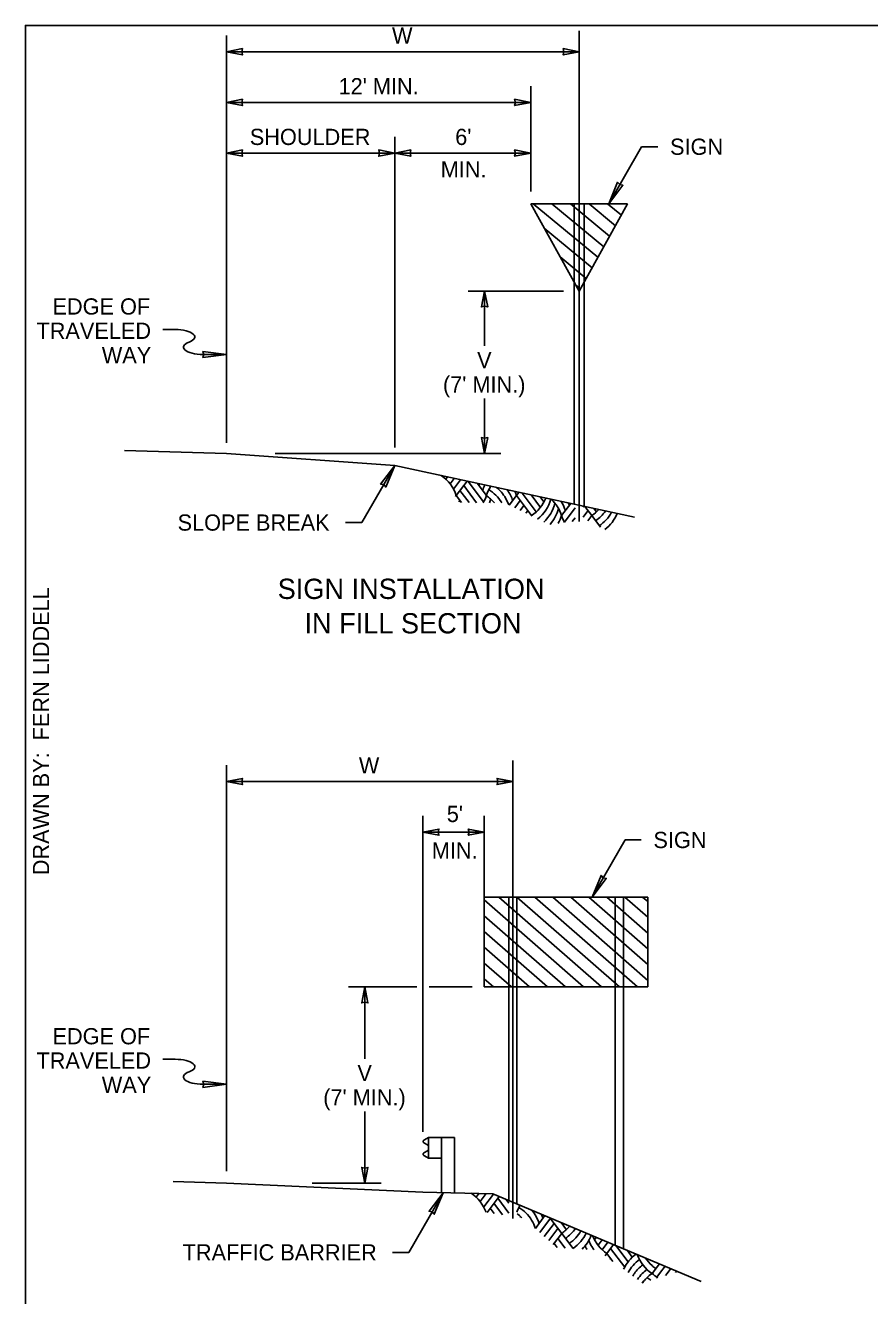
# Model space of a CAD drawing. Extents: x 99862 to 104211, y 98939 to 102076.
# Drawn here: x 99862 to 100694, y 100822 to 102076 of the extents above; entities that cross this region are included whole.
import ezdxf

# ---------------------------------------------------------------- set-up
doc = ezdxf.new("R2010")
doc.units = 0
for name, color, linetype in [('Level 1', 7, 'Continuous'), ('Level 14', 7, 'Continuous'), ('Level 15', 7, 'Continuous'), ('Level 2', 7, 'Continuous'), ('Level 20', 7, 'Continuous'), ('Level 6', 7, 'Continuous'), ('Level 62', 7, 'Continuous')]:
    doc.layers.add(name, color=color, linetype=linetype)

msp = doc.modelspace()

# ---------------------------------------------------------------- linework, layer by layer
at = {"layer": 'Level 1'}
msp.add_lwpolyline([(99862, 99999.5), (103151, 99999.5), (103151, 102075.5), (99862, 102075.5)], close=True, dxfattribs=at)
msp.add_lwpolyline([(99862, 99999.5), (103151, 99999.5), (103151, 102075.5), (99862, 102075.5)], close=True, dxfattribs=at)
at = {"layer": 'Level 14'}
for p, q in [((100009.7, 101775.4), (99997.4, 101775.4)), ((100056.2, 101750.8), (100037, 101750.8)), ((100009.7, 101055.4), (99997.4, 101055.4)), ((100056.2, 101030.8), (100037, 101030.8))]:
    msp.add_line(p, q, dxfattribs=at)
for points in [[(100060.3, 101750.8), (100036.9, 101747.8), (100038, 101750.8), (100036.9, 101753.9)], [(100060.3, 101030.8), (100036.9, 101027.7), (100038, 101030.8), (100036.9, 101033.8)]]:
    msp.add_lwpolyline(points, close=True, dxfattribs=at)
for centre, start_param, end_param in [((100009.8, 101768.2), 5.497747, 7.861127), ((100037, 101758), 2.356226, 4.712389), ((100009.8, 101048.2), 5.497747, 7.861127), ((100037, 101038), 2.356226, 4.712389)]:
    msp.add_ellipse(centre, major_axis=(19.2, 0), ratio=0.375, start_param=start_param, end_param=end_param, dxfattribs=at)
at = {"layer": 'Level 15'}
for p, q in [((100060.3, 102065.5), (100060.3, 101663.8)), ((100407.9, 102049.5), (100060.3, 102049.5)), ((100360.1, 102015.5), (100360.1, 101911.5)), ((100360.1, 101999.5), (100060.3, 101999.5)), ((100226.2, 101965.5), (100226.2, 101659.1)), ((100437, 101899.5), (100469.5, 101955.8)), ((100469.5, 101955.8), (100485.5, 101955.8)), ((100226.2, 101949.5), (100060.3, 101949.5)), ((100360.1, 101949.5), (100226.2, 101949.5)), ((100298.6, 101813.4), (100392.6, 101813.4)), ((100314.6, 101813.4), (100314.6, 101759.3)), ((100314.6, 101707.3), (100314.6, 101653.1)), ((100108.3, 101653.1), (100330.6, 101653.1)), ((100226.2, 101641.3), (100193.7, 101585)), ((100177.7, 101585), (100193.7, 101585)), ((100060.3, 101345.5), (100060.3, 100945.1)), ((100342.6, 101329.5), (100060.3, 101329.5)), ((100253.9, 101295.5), (100253.9, 100983.7)), ((100314.3, 101295.5), (100314.3, 101199)), ((100314.3, 101279.5), (100253.9, 101279.5)), ((100420.6, 101215.5), (100453.1, 101271.8)), ((100453.1, 101271.8), (100469.1, 101271.8)), ((100180.6, 101126.8), (100247.9, 101126.8)), ((100196.6, 101126.8), (100196.6, 101055.9)), ((100259.9, 101126.8), (100302.3, 101126.8)), ((100196.6, 101003.9), (100196.6, 100933.1)), ((100144.8, 100933.1), (100212.6, 100933.1)), ((100273.9, 100923.8), (100239.9, 100864.9)), ((100223.9, 100864.9), (100239.9, 100864.9))]:
    msp.add_line(p, q, dxfattribs=at)
for points in [[(100060.3, 102049.5), (100076, 102046.4), (100075.3, 102049.5), (100076, 102052.6)], [(100407.9, 102049.5), (100392.2, 102046.4), (100392.9, 102049.5), (100392.2, 102052.6)], [(100060.3, 101999.5), (100076, 101996.4), (100075.3, 101999.5), (100076, 102002.6)], [(100360.1, 101999.5), (100344.3, 101996.4), (100345.1, 101999.5), (100344.3, 102002.6)], [(100060.3, 101949.5), (100076, 101946.4), (100075.3, 101949.5), (100076, 101952.6)], [(100226.2, 101949.5), (100210.4, 101946.4), (100211.2, 101949.5), (100210.4, 101952.6)], [(100226.2, 101949.5), (100241.9, 101946.4), (100241.2, 101949.5), (100241.9, 101952.6)], [(100360.1, 101949.5), (100344.3, 101946.4), (100345.1, 101949.5), (100344.3, 101952.6)], [(100092.3, 101949.5), (100092.3, 101949.5), (100092.3, 101949.5), (100092.3, 101949.5)], [(100092.3, 101949.5), (100092.3, 101949.5), (100092.3, 101949.5), (100092.3, 101949.5)], [(100226.2, 101949.5), (100226.2, 101949.5), (100226.2, 101949.5), (100226.2, 101949.5)], [(100226.2, 101949.5), (100226.2, 101949.5), (100226.2, 101949.5), (100226.2, 101949.5)], [(100437, 101899.5), (100451, 101917.8), (100447.9, 101918.4), (100445.8, 101920.8)], [(100314.6, 101813.4), (100311.5, 101797.7), (100314.6, 101798.4), (100317.7, 101797.7)], [(100314.6, 101653.1), (100311.5, 101668.8), (100314.6, 101668.1), (100317.7, 101668.8)], [(100226.2, 101641.3), (100217.3, 101620), (100215.3, 101622.4), (100212.2, 101623)], [(100060.3, 101329.5), (100076, 101326.4), (100075.3, 101329.5), (100076, 101332.5)], [(100342.6, 101329.5), (100326.9, 101326.4), (100327.6, 101329.5), (100326.9, 101332.5)], [(100253.9, 101279.5), (100269.6, 101276.4), (100268.8, 101279.5), (100269.6, 101282.5)], [(100314.3, 101279.5), (100298.6, 101276.4), (100299.3, 101279.5), (100298.6, 101282.5)], [(100420.6, 101215.5), (100429.5, 101236.8), (100431.5, 101234.4), (100434.6, 101233.8)], [(100196.6, 101126.8), (100193.6, 101111.1), (100196.6, 101111.8), (100199.7, 101111.1)], [(100196.6, 100933.1), (100193.6, 100948.8), (100196.6, 100948.1), (100199.7, 100948.8)], [(100273.9, 100923.8), (100265, 100902.5), (100263, 100904.9), (100259.9, 100905.5)]]:
    msp.add_lwpolyline(points, close=True, dxfattribs=at)
at = {"layer": 'Level 2'}
for p, q in [((100407.9, 102070.3), (100407.9, 101586)), ((100360.1, 101899.5), (100455.7, 101899.5)), ((100407.9, 101813.4), (100360.1, 101899.5)), ((100362.6, 101899.5), (100426.4, 101846.7)), ((100380.9, 101899.5), (100432.2, 101857.1)), ((100399.3, 101899.5), (100437.9, 101867.5)), ((100403.1, 101899.5), (100403.1, 101822.3)), ((100407.9, 101813.4), (100455.7, 101899.5)), ((100412.7, 101899.5), (100412.7, 101822)), ((100417.6, 101899.5), (100443.7, 101877.9)), ((100435.9, 101899.5), (100449.5, 101888.3)), ((100373.5, 101875.3), (100420.6, 101836.3)), ((100389.1, 101847.2), (100414.8, 101825.9)), ((100403.1, 101822), (100403.1, 101603)), ((100404.7, 101819.2), (100409.1, 101815.5)), ((100412.7, 101822), (100412.7, 101600.9)), ((100060.3, 101653.1), (99959.8, 101656.2)), ((100060.3, 101653.1), (100226.2, 101641.3)), ((100226.2, 101641.3), (100462.4, 101590.2)), ((100342.6, 101350.3), (100342.6, 100898.4)), ((100314.3, 101215.5), (100314.3, 101126.8)), ((100314.3, 101215.5), (100475.7, 101215.5)), ((100412.1, 101126.8), (100314.3, 101212.6)), ((100429.9, 101126.8), (100328.8, 101215.5)), ((100338.5, 101126.8), (100338.5, 101215.5)), ((100447.6, 101126.8), (100346.5, 101215.5)), ((100346.6, 101126.8), (100346.6, 101215.5)), ((100465.3, 101126.8), (100364.2, 101215.5)), ((100475.7, 101133.2), (100381.9, 101215.5)), ((100475.7, 101148.8), (100399.7, 101215.5)), ((100475.7, 101164.4), (100417.4, 101215.5)), ((100475.7, 101179.9), (100435.1, 101215.5)), ((100443.4, 101126.8), (100443.4, 101215.5)), ((100451.5, 101126.8), (100451.5, 101215.5)), ((100475.7, 101195.5), (100452.8, 101215.5)), ((100475.7, 101211), (100470.5, 101215.5)), ((100475.7, 101215.5), (100475.7, 101126.8)), ((100394.4, 101126.8), (100314.3, 101197.1)), ((100376.7, 101126.8), (100314.3, 101181.5)), ((100359, 101126.8), (100314.3, 101166)), ((100341.3, 101126.8), (100314.3, 101150.4)), ((100323.5, 101126.8), (100314.3, 101134.9)), ((100314.3, 101126.8), (100475.7, 101126.8)), ((100338.5, 101126.8), (100338.5, 100916.1)), ((100346.6, 101126.8), (100346.6, 100912.7)), ((100443.4, 101126.8), (100443.4, 100872)), ((100451.5, 101126.8), (100451.5, 100868.6)), ((100254.8, 100975.7), (100257.8, 100977.4)), ((100254.8, 100973), (100258.5, 100971)), ((100259.3, 100978.2), (100257.8, 100977.4)), ((100259.2, 100978.2), (100285.1, 100978.2)), ((100259.3, 100978.2), (100259.3, 100958)), ((100272.2, 100978.2), (100272.2, 100923.8)), ((100285.1, 100978.2), (100285.1, 100923.6)), ((100254.7, 100960.5), (100257.8, 100958.7)), ((100254.8, 100963.2), (100258.5, 100965.2)), ((100259.3, 100966.5), (100259.3, 100969.6)), ((100259.3, 100958), (100257.8, 100958.7)), ((100259.3, 100958), (100272.2, 100958)), ((100060.3, 100933.1), (100007.6, 100934.7)), ((100060.3, 100933.1), (100253.9, 100924.2)), ((100253.9, 100924.2), (100322.7, 100922.8)), ((100322.7, 100922.8), (100528.1, 100836.3))]:
    msp.add_line(p, q, dxfattribs=at)
for centre, radius, start, end in [((100255.5, 100974.3), 1.55, 118.2399, 241.2772), ((100255.5, 100961.8), 1.55, 118.3269, 239.7049), ((100257.8, 100969.6), 1.54, 359.9913, 61.47), ((100257.8, 100966.5), 1.54, 298.53, 359.9913)]:
    msp.add_arc(centre, radius, start, end, dxfattribs=at)
at = {"layer": 'Level 6'}
for p, q in [((100276.5, 101627.7), (100278.2, 101630)), ((100280.6, 101623.2), (100284.6, 101628.6)), ((100284, 101617.9), (100291, 101627.2)), ((100286.7, 101611.6), (100297.4, 101625.9)), ((100298.4, 101625.6), (100313.7, 101605.3)), ((100290.4, 101616.5), (100299.3, 101604.7)), ((100294.1, 101621.5), (100306.8, 101604.6)), ((100307.3, 101623.7), (100316.4, 101611.6)), ((100346.1, 101611.6), (100348.5, 101614.8)), ((100351.6, 101614.1), (100365.6, 101595.5)), ((100360.5, 101612.2), (100369.7, 101599.9)), ((100285.9, 101610.6), (100286.7, 101611.6)), ((100286.7, 101611.6), (100291.8, 101604.7)), ((100289.4, 101605.3), (100290.4, 101606.6)), ((100339, 101602.1), (100346.1, 101611.6)), ((100344.4, 101599.5), (100349.8, 101606.6)), ((100346.1, 101611.6), (100360.9, 101591.8)), ((100349.8, 101596.8), (100353.5, 101601.7)), ((100369.3, 101610.3), (100373.1, 101605.3)), ((100390.6, 101591.8), (100399.6, 101603.8)), ((100393.3, 101585.5), (100403.9, 101599.6)), ((100411.9, 101600.3), (100412.4, 101601)), ((100413.6, 101600.7), (100420.3, 101591.8)), ((100355.3, 101594.1), (100357.2, 101596.7)), ((100360.7, 101591.5), (100360.9, 101591.8)), ((100360.9, 101591.8), (100361.4, 101591.2)), ((100401.1, 101585.9), (100403.9, 101589.7)), ((100411.9, 101590.4), (100416.6, 101596.7)), ((100416.6, 101586.8), (100420.3, 101591.8)), ((100420.3, 101591.8), (100428.8, 101580.5)), ((100422.5, 101598.8), (100425, 101595.5)), ((100416.6, 101586.8), (100416.6, 101586.8)), ((100306.2, 100919.5), (100308.9, 100923.1)), ((100310.3, 100915.1), (100316.2, 100922.9)), ((100313.8, 100909.8), (100323.3, 100922.5)), ((100317.1, 100904.3), (100329, 100920.2)), ((100323.9, 100913.3), (100332.4, 100902)), ((100327.6, 100918.3), (100338.6, 100903.6)), ((100335.7, 100917.3), (100338.6, 100913.5)), ((100320.1, 100908.4), (100324, 100903.3)), ((100364.7, 100888.6), (100374.1, 100901.2)), ((100369.1, 100884.6), (100379.5, 100898.5)), ((100379.1, 100899), (100390.7, 100883.6)), ((100373.5, 100880.6), (100383.3, 100893.5)), ((100378, 100876.6), (100387, 100888.6)), ((100390, 100894.5), (100395.3, 100887.3)), ((100382.4, 100872.6), (100390.7, 100883.6)), ((100383.3, 100873.7), (100386.3, 100869.7)), ((100387, 100878.7), (100394.1, 100869.2)), ((100390.7, 100883.6), (100401.9, 100868.7)), ((100423.1, 100877.3), (100424.9, 100879.8)), ((100426.5, 100872), (100430.5, 100877.4)), ((100430.6, 100867.5), (100436.2, 100875)), ((100435.2, 100863.8), (100441.8, 100872.6)), ((100433.5, 100861.6), (100435.2, 100863.8)), ((100435.2, 100863.8), (100441.1, 100856)), ((100438.9, 100868.8), (100452.8, 100850.4)), ((100444.2, 100871.6), (100456.2, 100855.7)), ((100455.1, 100867), (100460.3, 100860.1)), ((100438.3, 100858), (100438.9, 100858.9)), ((100479.8, 100844), (100487, 100853.6)), ((100487.2, 100844), (100492.6, 100851.2)), ((100494.6, 100844), (100498.2, 100848.9)), ((100484.4, 100840.3), (100487.2, 100844)), ((100493.1, 100842), (100494.6, 100844)), ((100502.9, 100845.2), (100503.9, 100846.5))]:
    msp.add_line(p, q, dxfattribs=at)
for centre, start, end in [((100250.9, 101600.2), 17.6434, 56.0947), ((100344.8, 101610.1), 159.5467, 162.3566), ((100348.5, 101605.1), 153.2388, 162.3566), ((100352.2, 101600.2), 146.7442, 162.3566), ((100299.1, 101585.4), 31.3316, 58.4874), ((100302.8, 101590.3), 40.9413, 51.2149), ((100302.8, 101590.3), 18.7263, 40.9414), ((100306.6, 101595.2), 17.6434, 35.9283), ((100310.3, 101600.2), 17.6434, 24.3134), ((100280.6, 101623), 330.6518, 342.3566), ((100295.4, 101580.4), 39.8382, 56.0964), ((100284.3, 101618), 338.9197, 345.0113), ((100299.1, 101585.4), 30.4881, 31.3317), ((100340, 101623), 303.9036, 338.33), ((100343.7, 101618), 308.1554, 344.5515), ((100347.4, 101613.1), 312.8471, 346.3199), ((100354.8, 101580.4), 17.6434, 47.0532), ((100358.5, 101585.4), 31.3316, 33.0188), ((100358.5, 101585.4), 17.6434, 31.3317), ((100362.2, 101590.3), 17.6434, 21.868), ((100351.1, 101608.1), 318.4602, 345.7713), ((100354.8, 101603.2), 329.6871, 342.3566), ((100426.4, 101603.2), 197.6435, 208.9334), ((100399.4, 101623), 303.9036, 317.8918), ((100403.1, 101618), 303.9036, 324.7989), ((100406.8, 101613.1), 303.9036, 331.3675), ((100410.5, 101608.1), 307.1427, 337.7201), ((100414.2, 101580.4), 19.0136, 19.4909), ((100422.7, 101598.2), 200.8778, 201.7831), ((100280.6, 100892), 19.3393, 56.0945), ((100381.9, 100892), 148.9555, 160.2414), ((100325.2, 100872.2), 45.5471, 55.2753), ((100328.9, 100877.2), 31.3316, 58.4874), ((100314, 100909.9), 343.631, 345.0113), ((100332.6, 100882.1), 17.6434, 40.6931), ((100336.3, 100887.1), 17.6434, 24.5032), ((100328.9, 100877.2), 17.6658, 31.3317), ((100369.7, 100914.8), 303.9036, 320.3127), ((100373.4, 100909.9), 303.9036, 325.2256), ((100377.1, 100904.9), 303.9036, 330.0509), ((100380.9, 100900), 303.9036, 334.8258), ((100384.6, 100895), 314.2423, 339.5846), ((100452.5, 100890.1), 200.8778, 211.332), ((100456.2, 100895), 201.386, 236.0964), ((100448.8, 100885.1), 201.4344, 207.4578), ((100452.5, 100890.1), 211.3319, 217.2558), ((100485.9, 100832.6), 125.4637, 155.4997), ((100500.7, 100875.2), 199.3972, 236.0964), ((100489.6, 100827.7), 126.3063, 152.7121), ((100493.3, 100822.7), 127.1006, 145.4911), ((100497, 100817.8), 126.331, 135.7128), ((100504.4, 100880.2), 213.4609, 228.9599), ((100504.4, 100880.2), 228.9599, 236.0964), ((100493.3, 100822.7), 145.491, 149.9457), ((100497, 100817.8), 135.7127, 147.1937), ((100500.7, 100812.8), 123.9036, 144.4496), ((100451.4, 100802.9), 58.4099, 59.3021), ((100455.1, 100807.9), 51.5617, 58.5465), ((100458.8, 100812.8), 45.2234, 56.0963)]:
    msp.add_arc(centre, 37.6, start, end, dxfattribs=at)

# ---------------------------------------------------------------- texts
at = {"layer": 'Level 2'}
for s, p in [('SIGN INSTALLATION', (100110.7, 101509.6)), ('IN FILL SECTION', (100137.1, 101475.6))]:
    msp.add_text(s, height=20, dxfattribs=at).set_placement(p)
at = {"layer": 'Level 20'}
for s, p in [('W', (100223.4, 102057.5)), ("12' MIN.", (100170.7, 102007.5)), ('SHOULDER', (100083.2, 101957.5)), ("6'", (100285.7, 101957.5)), ('SIGN', (100497.5, 101947.8)), ('MIN.', (100271.4, 101925.5)), ('EDGE OF', (99888.7, 101790.2)), ('TRAVELED', (99872.9, 101766.2)), ('WAY', (99937.3, 101742.2)), ('V', (100307.3, 101737.3)), ("(7' MIN.)", (100273.6, 101713.3)), ('SLOPE BREAK', (100012, 101577)), ('W', (100190.7, 101337.5)), ("5'", (100277.4, 101289.5)), ('SIGN', (100481.1, 101263.8)), ('MIN.', (100262.6, 101253.5)), ('EDGE OF', (99888.7, 101070.2)), ('TRAVELED', (99872.9, 101046.2)), ('V', (100189.3, 101033.9)), ('WAY', (99937.3, 101022.2)), ("(7' MIN.)", (100155.6, 101009.9)), ('TRAFFIC BARRIER', (100017, 100856.9))]:
    msp.add_text(s, height=16, dxfattribs=at).set_placement(p)
at = {"layer": 'Level 62'}
msp.add_text('DRAWN BY:  FERN LIDDELL', height=16, rotation=90, dxfattribs=at).set_placement((99885.4, 101237))

doc.saveas('drawing.dxf')
